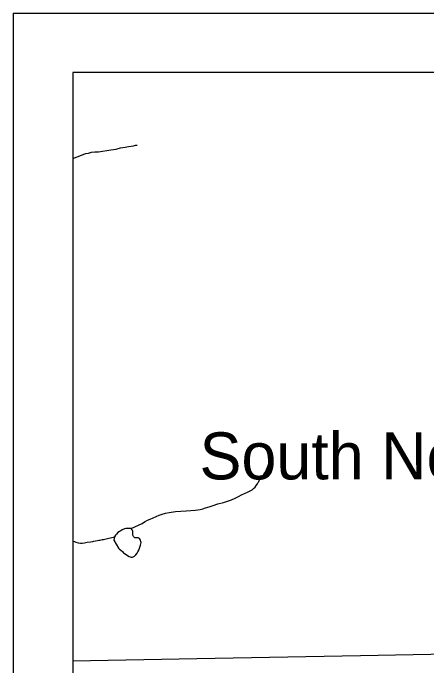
# Model space of a CAD drawing. Extents: x 10.6 to 44.6, y -2.6 to 23.4.
# Drawn here: x 13.103 to 13.799, y 21.329 to 22.426 of the extents above; entities that cross this region are included whole.
import ezdxf

# ---------------------------------------------------------------- set-up
doc = ezdxf.new("R2010")
doc.units = 0
for name, color, linetype in [('GM_X_County', 7, 'Continuous'), ('GM_X_County_Road', 7, 'Continuous'), ('GM_X_Minor_Lake', 7, 'Continuous'), ('GM_X_Minor_River', 7, 'Continuous'), ('GM_X_Township', 7, 'Continuous'), ('GM_X_Unincorporated_Text', 7, 'Continuous'), ('SH_Data', 7, 'Continuous')]:
    doc.layers.add(name, color=color, linetype=linetype)

msp = doc.modelspace()

# ---------------------------------------------------------------- linework, layer by layer
at = {"layer": 'GM_X_County'}
msp.add_lwpolyline([(20.0033, 15.5302), (20.0033, 22.3267), (13.2033, 22.3267), (13.2033, 15.5267), (19.8413, 15.5267)], dxfattribs=at)
at = {"layer": 'GM_X_County_Road'}
msp.add_lwpolyline([(13.2033, 21.3379), (13.4118, 21.3419), (13.687, 21.3468), (13.9527, 21.3521), (14.0683, 21.3546), (14.2259, 21.3565), (14.2819, 21.357), (14.3057, 21.3568)], dxfattribs=at)
at = {"layer": 'GM_X_Minor_Lake'}
for points in [[(13.2976, 21.5603), (13.2948, 21.5604), (13.2926, 21.5603), (13.2899, 21.5595), (13.2865, 21.5579), (13.2839, 21.5563), (13.2816, 21.5555), (13.279, 21.5536), (13.2768, 21.5509), (13.2753, 21.5489), (13.2735, 21.5462), (13.2728, 21.5432), (13.2721, 21.5409)], [(13.2721, 21.5409), (13.28, 21.5274), (13.2819, 21.5255), (13.2838, 21.5237), (13.2866, 21.5214), (13.2885, 21.5196), (13.2904, 21.5181), (13.2927, 21.5166), (13.2954, 21.5148), (13.2981, 21.5133), (13.3016, 21.5123), (13.3035, 21.5123), (13.3069, 21.5139), (13.3091, 21.5159), (13.3117, 21.5186), (13.3128, 21.5213), (13.3143, 21.5236), (13.3153, 21.527), (13.3161, 21.5289), (13.3171, 21.5324), (13.3178, 21.5347), (13.3182, 21.5366), (13.3178, 21.5385), (13.317, 21.5407), (13.3154, 21.5434), (13.3131, 21.5444), (13.3112, 21.5448), (13.3077, 21.5447), (13.3054, 21.5466), (13.3042, 21.5488), (13.3042, 21.5511), (13.3041, 21.5534), (13.3041, 21.5556), (13.3033, 21.5579), (13.3013, 21.5601), (13.2976, 21.5603)]]:
    msp.add_lwpolyline(points, dxfattribs=at)
at = {"layer": 'GM_X_Minor_River'}
for points in [[(13.2033, 22.1821), (13.2179, 22.1879), (13.2216, 22.1892), (13.2254, 22.1904), (13.2296, 22.1912), (13.2345, 22.1925), (13.2402, 22.193), (13.2463, 22.1935), (13.2531, 22.1944), (13.2603, 22.1953), (13.2671, 22.1966), (13.2759, 22.1979), (13.2834, 22.2), (13.291, 22.2013), (13.2967, 22.2022), (13.3012, 22.203), (13.3054, 22.2035), (13.3088, 22.2044), (13.3103, 22.2044), (13.3115, 22.2044)], [(13.3013, 21.5601), (13.3198, 21.5689), (13.322, 21.5701), (13.325, 21.5721), (13.3288, 21.574), (13.3333, 21.576), (13.3382, 21.5784), (13.3435, 21.5804), (13.3484, 21.5824), (13.3537, 21.5845), (13.359, 21.5861), (13.3654, 21.5874), (13.376, 21.5887), (13.3848, 21.5893), (13.3939, 21.5899), (13.4019, 21.5904), (13.4087, 21.591), (13.4136, 21.5915), (13.4174, 21.5923), (13.4216, 21.5935), (13.4265, 21.5948), (13.4325, 21.5968), (13.4393, 21.5989), (13.4469, 21.6017), (13.4567, 21.6038), (13.4635, 21.6062), (13.4703, 21.6087), (13.476, 21.6111), (13.4816, 21.6138), (13.4869, 21.6166), (13.4918, 21.619), (13.4967, 21.6214), (13.5012, 21.6234), (13.5046, 21.6254), (13.5072, 21.6273), (13.5098, 21.63), (13.5113, 21.6323), (13.5135, 21.6354), (13.5157, 21.6389), (13.5179, 21.6424), (13.5201, 21.6458), (13.5223, 21.6485), (13.5242, 21.6509), (13.526, 21.6536), (13.5275, 21.6563), (13.529, 21.6593), (13.5304, 21.6635), (13.5322, 21.6678), (13.534, 21.6724), (13.5358, 21.677), (13.5373, 21.6796), (13.5387, 21.6831), (13.5391, 21.6835), (13.5391, 21.6839)], [(13.2033, 21.5392), (13.2063, 21.5383), (13.2086, 21.5372), (13.2121, 21.5362), (13.2163, 21.5355), (13.2189, 21.5356), (13.2227, 21.536), (13.2276, 21.5373), (13.2329, 21.5378), (13.2367, 21.5386), (13.2386, 21.539), (13.2413, 21.5398), (13.2447, 21.5403), (13.247, 21.5407)], [(13.247, 21.5407), (13.2492, 21.5408), (13.253, 21.542), (13.2549, 21.542), (13.2572, 21.5425), (13.2735, 21.5462)]]:
    msp.add_lwpolyline(points, dxfattribs=at)
at = {"layer": 'GM_X_Township'}
msp.add_lwpolyline([(15.2363, 22.3267), (13.2033, 22.3267), (13.2033, 20.8217)], dxfattribs=at)
at = {"layer": 'SH_Data'}
for q in [(20.1028, 22.4265), (13.1028, 15.4265)]:
    msp.add_line((13.1028, 22.4265), q, dxfattribs=at)

# ---------------------------------------------------------------- texts
at = {"layer": 'GM_X_Unincorporated_Text'}
msp.add_text('South Newbury', height=0.078977, rotation=0, dxfattribs=at).set_placement((13.4163, 21.6428))

doc.saveas('drawing.dxf')
